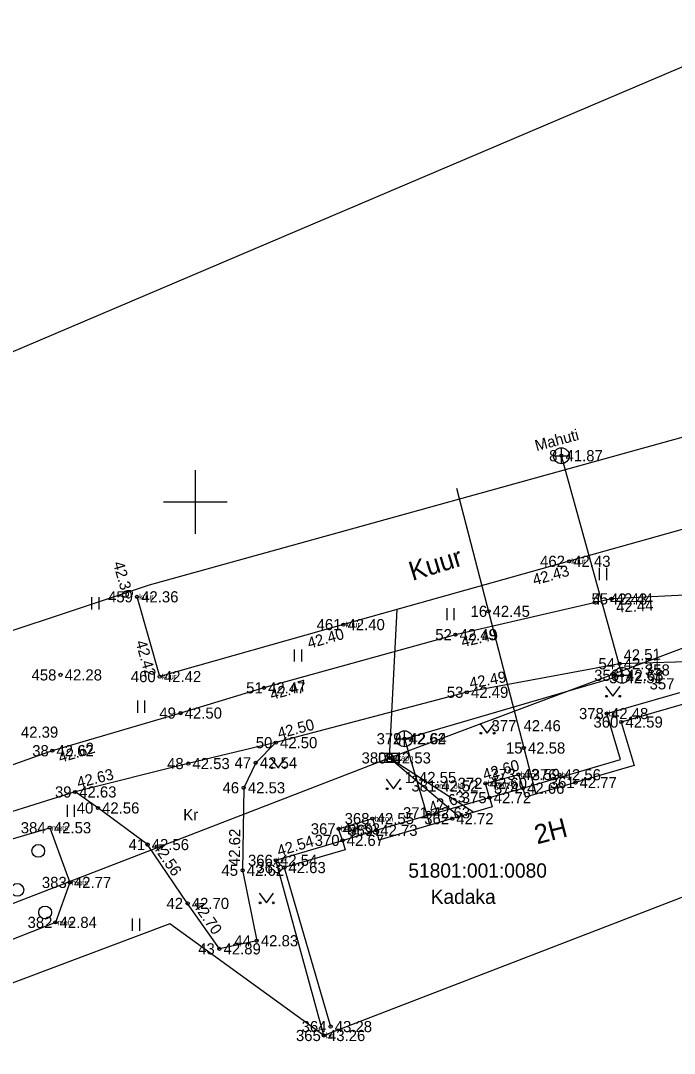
# Model space of a CAD drawing. Extents: x 505800 to 507326, y 6540058 to 6542128.
# Drawn here: x 506089 to 506130.1, y 6540215.4 to 6540280.2 of the extents above; entities that cross this region are included whole.
import ezdxf

# ---------------------------------------------------------------- set-up
doc = ezdxf.new("R2010")
doc.units = 0
for name, color, linetype in [('ELRAJATISMP', 7, 'Continuous'), ('HALJASTUS', 7, 'Continuous'), ('HOONE', 7, 'Continuous'), ('HOONEDET', 7, 'Continuous'), ('KKAEV', 7, 'Continuous'), ('KORGUS-EH2000', 7, 'Continuous'), ('KTRASS', 7, 'Continuous'), ('MAAMUDEL', 7, 'Continuous'), ('MOOTKORG-EH2000', 7, 'Continuous'), ('MOOTMPUNKT', 7, 'Continuous'), ('MOOTNR', 7, 'Continuous'), ('MOOTPIIR', 7, 'Continuous'), ('MPKAABEL', 7, 'Continuous'), ('MPOHULIIN', 7, 'Continuous'), ('PIIR', 7, 'Continuous'), ('POST', 7, 'Continuous'), ('RAJATIS', 7, 'Continuous'), ('TEE', 7, 'Continuous'), ('VORK', 7, 'Continuous')]:
    doc.layers.add(name, color=color, linetype=linetype)

msp = doc.modelspace()

# ---------------------------------------------------------------- linework, layer by layer
at = {"layer": 'ELRAJATISMP'}
for p, q in [((506112.053, 6540234.226), (506112.053, 6540233.629)), ((506112.325, 6540234.226), (506112.325, 6540233.629))]:
    msp.add_line(p, q, dxfattribs=at)
msp.add_lwpolyline([(506111.592, 6540234.226), (506112.786, 6540234.226), (506112.786, 6540233.629), (506111.592, 6540233.629)], close=True, dxfattribs=at)
at = {"layer": 'HALJASTUS'}
for p, q in [((506125.351, 6540245.86), (506125.351, 6540245.098)), ((506125.806, 6540245.86), (506125.806, 6540245.098)), ((506093.482, 6540244.017), (506093.482, 6540243.256)), ((506093.937, 6540244.017), (506093.937, 6540243.256)), ((506115.782, 6540243.336), (506115.782, 6540242.575)), ((506116.237, 6540243.336), (506116.237, 6540242.575)), ((506106.213, 6540240.732), (506106.213, 6540239.971)), ((506106.668, 6540240.732), (506106.668, 6540239.971)), ((506125.757, 6540238.405), (506126.22, 6540237.798)), ((506126.22, 6540237.798), (506126.666, 6540238.405)), ((506096.364, 6540237.527), (506096.364, 6540236.766)), ((506096.819, 6540237.527), (506096.819, 6540236.766)), ((506117.869, 6540236.081), (506118.333, 6540235.475)), ((506118.333, 6540235.475), (506118.778, 6540236.081)), ((506104.737, 6540233.918), (506105.201, 6540233.311)), ((506105.201, 6540233.311), (506105.646, 6540233.918)), ((506111.984, 6540232.596), (506112.447, 6540231.989)), ((506112.447, 6540231.989), (506112.893, 6540232.596)), ((506091.951, 6540230.988), (506091.951, 6540230.227)), ((506092.406, 6540230.988), (506092.406, 6540230.227)), ((506104.008, 6540225.43), (506104.471, 6540224.824)), ((506104.471, 6540224.824), (506104.917, 6540225.43)), ((506096.045, 6540223.837), (506096.045, 6540223.076)), ((506096.5, 6540223.837), (506096.5, 6540223.076))]:
    msp.add_line(p, q, dxfattribs=at)
msp.add_lwpolyline([(506091.221, 6540223.598), (506086.055, 6540221.567), (506084.601, 6540227.684), (506090.863, 6540229.542), (506092.12, 6540226.107), (506091.221, 6540223.598)], dxfattribs=at)
for centre, radius in [((506125.819, 6540237.798), 0.055), ((506126.648, 6540237.798), 0.055), ((506117.932, 6540235.475), 0.055), ((506118.76, 6540235.475), 0.055), ((506104.8, 6540233.311), 0.055), ((506105.628, 6540233.311), 0.055), ((506112.046, 6540231.989), 0.055), ((506112.875, 6540231.989), 0.055), ((506090.14, 6540228.09), 0.4), ((506088.836, 6540225.641), 0.4), ((506090.575, 6540224.221), 0.4), ((506104.07, 6540224.824), 0.055), ((506104.899, 6540224.824), 0.055)]:
    msp.add_circle(centre, radius, dxfattribs=at)
at = {"layer": 'HOONE'}
for p, q in [((506130.639, 6540237.309), (506126.746, 6540236.177)), ((506123.864, 6540232.378), (506120.736, 6540231.461)), ((506118.476, 6540231.431), (506120.57, 6540232.025)), ((506120.57, 6540232.025), (506120.736, 6540231.461)), ((506118.476, 6540231.431), (506118.648, 6540230.848)), ((506118.648, 6540230.848), (506111.53, 6540228.77)), ((506109.245, 6540228.75), (506111.352, 6540229.381)), ((506111.352, 6540229.381), (506111.53, 6540228.77)), ((506109.245, 6540228.75), (506109.418, 6540228.155))]:
    msp.add_line(p, q, dxfattribs=at)
for points in [[(506132.518, 6540254.195), (506133.851, 6540249.184), (506123.465, 6540246.272), (506109.297, 6540242.297), (506097.771, 6540239.032), (506096.343, 6540244.043)], [(506126.746, 6540236.177), (506127.543, 6540233.458), (506123.864, 6540232.378)], [(506109.418, 6540228.155), (506105.588, 6540227.041), (506108.496, 6540217.056)]]:
    msp.add_lwpolyline(points, dxfattribs=at)
at = {"layer": 'HOONEDET'}
for p, q in [((506125.837, 6540236.712), (506130.426, 6540238.044)), ((506126.686, 6540233.82), (506125.837, 6540236.712)), ((506120.57, 6540232.025), (506126.686, 6540233.82)), ((506111.352, 6540229.381), (506118.476, 6540231.431)), ((506105.058, 6540227.498), (506109.245, 6540228.75)), ((506108.07, 6540216.496), (506105.058, 6540227.498))]:
    msp.add_line(p, q, dxfattribs=at)
at = {"layer": 'KKAEV'}
for p, q in [((506122.982, 6540252.403), (506122.982, 6540253.403)), ((506122.482, 6540252.903), (506123.482, 6540252.903)), ((506126.792, 6540238.616), (506126.792, 6540239.616)), ((506126.292, 6540239.116), (506127.292, 6540239.116)), ((506113.134, 6540234.63), (506113.134, 6540235.63)), ((506112.634, 6540235.13), (506113.634, 6540235.13))]:
    msp.add_line(p, q, dxfattribs=at)
for centre in [(506122.982, 6540252.903), (506126.792, 6540239.116), (506113.134, 6540235.13)]:
    msp.add_circle(centre, 0.5, dxfattribs=at)
at = {"layer": 'KORGUS-EH2000'}
for centre in [(506122.982, 6540252.903), (506123.465, 6540246.272), (506096.343, 6540244.043), (506126.133, 6540243.916), (506118.402, 6540243.131), (506109.297, 6540242.297), (506116.327, 6540241.664), (506126.638, 6540239.842), (506091.541, 6540239.138), (506097.771, 6540239.032), (506126.792, 6540239.116), (506104.313, 6540238.326), (506117.049, 6540238.049), (506099.073, 6540236.742), (506125.837, 6540236.712), (506126.746, 6540236.177), (506105.059, 6540234.886), (506113.134, 6540235.13), (506091.024, 6540234.378), (506120.624, 6540234.55), (506099.56, 6540233.572), (506103.793, 6540233.616), (506112.189, 6540233.927), (506120.291, 6540232.886), (506122.866, 6540232.868), (506113.78, 6540232.698), (506118.219, 6540232.328), (506123.864, 6540232.378), (506092.451, 6540231.789), (506103.04, 6540232.052), (506115.177, 6540232.167), (506120.57, 6540232.025), (506118.476, 6540231.431), (506093.889, 6540230.784), (506114.65, 6540230.481), (506111.125, 6540230.116), (506116.124, 6540230.107), (506090.863, 6540229.542), (506108.999, 6540229.472), (506111.352, 6540229.381), (506097.004, 6540228.485), (506109.245, 6540228.75), (506105.058, 6540227.498), (506105.588, 6540227.041), (506102.972, 6540226.871), (506092.12, 6540226.107), (506099.521, 6540224.79), (506091.221, 6540223.598), (506103.856, 6540222.445), (506101.513, 6540221.937), (506108.496, 6540217.056), (506108.07, 6540216.496)]:
    msp.add_circle(centre, 0.1, dxfattribs=at)
at = {"layer": 'KTRASS'}
for p, q in [((506116.398, 6540250.872), (506121.375, 6540231.648)), ((506113.134, 6540235.13), (506114.719, 6540229.701))]:
    msp.add_line(p, q, dxfattribs=at)
msp.add_lwpolyline([(506113.134, 6540235.13), (506126.792, 6540239.116), (506122.982, 6540252.903)], dxfattribs=at)
at = {"layer": 'MOOTMPUNKT'}
for centre in [(506122.982, 6540252.903), (506123.465, 6540246.272), (506096.343, 6540244.043), (506126.133, 6540243.916), (506118.402, 6540243.131), (506109.297, 6540242.297), (506116.327, 6540241.664), (506126.638, 6540239.842), (506091.541, 6540239.138), (506097.771, 6540239.032), (506126.792, 6540239.116), (506104.313, 6540238.326), (506117.049, 6540238.049), (506099.073, 6540236.742), (506125.837, 6540236.712), (506126.746, 6540236.177), (506105.059, 6540234.886), (506113.134, 6540235.13), (506091.024, 6540234.378), (506120.624, 6540234.55), (506099.56, 6540233.572), (506103.793, 6540233.616), (506112.189, 6540233.927), (506120.291, 6540232.886), (506122.866, 6540232.868), (506113.78, 6540232.698), (506118.219, 6540232.328), (506123.864, 6540232.378), (506092.451, 6540231.789), (506103.04, 6540232.052), (506115.177, 6540232.167), (506120.57, 6540232.025), (506118.476, 6540231.431), (506093.889, 6540230.784), (506114.65, 6540230.481), (506111.125, 6540230.116), (506116.124, 6540230.107), (506090.863, 6540229.542), (506108.999, 6540229.472), (506111.352, 6540229.381), (506097.004, 6540228.485), (506109.245, 6540228.75), (506105.058, 6540227.498), (506105.588, 6540227.041), (506102.972, 6540226.871), (506092.12, 6540226.107), (506099.521, 6540224.79), (506091.221, 6540223.598), (506103.856, 6540222.445), (506101.513, 6540221.937), (506108.496, 6540217.056), (506108.07, 6540216.496)]:
    msp.add_circle(centre, 0.1, dxfattribs=at)
at = {"layer": 'MOOTPIIR'}
for points in [[(506083.03, 6540240.114), (506097.119, 6540244.795), (506135.023, 6540255.311), (506160.43, 6540256.455), (506171.091, 6540256.503), (506184.044, 6540258.184), (506197.806, 6540260.288), (506211.896, 6540262.383), (506227.932, 6540267.786), (506240.253, 6540270.959), (506245.955, 6540263.864)], [(506248.469, 6540250.071), (506234.931, 6540239.99), (506231.591, 6540236.406), (506193.196, 6540222.875), (506188.596, 6540225.549), (506168.901, 6540229.957), (506140.91, 6540229.168), (506108.07, 6540216.496), (506098.399, 6540223.506), (506079.917, 6540216.55)]]:
    msp.add_lwpolyline(points, dxfattribs=at)
at = {"layer": 'MPKAABEL'}
for q in [(506112.67, 6540243.243), (506116.557, 6540230.238)]:
    msp.add_line((506112.189, 6540233.927), q, dxfattribs=at)
at = {"layer": 'MPOHULIIN'}
for points in [[(506112.189, 6540233.927), (506153.828, 6540249.522), (506196.936, 6540256.778), (506240.207, 6540264.027), (506283.784, 6540271.755), (506305.802, 6540315.044)], [(506023.288, 6540193.167), (506046.819, 6540209.126), (506079.898, 6540221.464), (506112.189, 6540233.927), (506117.49, 6540230.51)]]:
    msp.add_lwpolyline(points, dxfattribs=at)
at = {"layer": 'PIIR'}
msp.add_lwpolyline([(506075.94, 6540254.08), (506092.1, 6540260.96), (506133.36, 6540278.52), (506141.06, 6540246.81), (506150.17, 6540208.02), (506090.32, 6540182.64), (506081.75, 6540225.93), (506080.52, 6540231.87)], close=True, dxfattribs=at)
at = {"layer": 'POST'}
msp.add_circle((506112.189, 6540233.927), 0.25, dxfattribs=at)
at = {"layer": 'TEE'}
for points in [[(506250.031, 6540264.042), (506237.432, 6540259.066), (506223.872, 6540254.219), (506212.634, 6540251.013), (506200.022, 6540248.8), (506187.383, 6540247.629), (506174.426, 6540246.673), (506168.123, 6540246.063), (506162.988, 6540245.422), (506156.937, 6540244.719), (506147.401, 6540244.066), (506139.254, 6540244.367), (506135.743, 6540244.402), (506126.133, 6540243.916), (506116.327, 6540241.664), (506104.313, 6540238.326), (506099.073, 6540236.742), (506091.024, 6540234.378), (506084.768, 6540232.16)], [(506136.149, 6540239.864), (506135.937, 6540240.063), (506132.254, 6540239.999), (506126.638, 6540239.842), (506117.049, 6540238.049), (506105.059, 6540234.886), (506099.56, 6540233.572), (506092.451, 6540231.789), (506085.515, 6540229.625), (506076.748, 6540225.83), (506064.781, 6540220.419), (506053.702, 6540216.033), (506042.573, 6540211.964), (506030.369, 6540207.528), (506023.645, 6540204.818), (506020.115, 6540202.573), (506018.326, 6540200.153), (506016.859, 6540196.696), (506016.712, 6540193.498), (506017.316, 6540188.473)], [(506105.059, 6540234.886), (506103.793, 6540233.616), (506103.04, 6540232.052), (506102.972, 6540226.871), (506103.856, 6540222.445), (506101.513, 6540221.937), (506099.521, 6540224.79), (506097.004, 6540228.485), (506093.889, 6540230.784), (506092.451, 6540231.789)], [(506118.476, 6540231.431), (506118.219, 6540232.328), (506120.291, 6540232.886), (506120.57, 6540232.025)], [(506109.245, 6540228.75), (506108.999, 6540229.472), (506111.125, 6540230.116), (506111.352, 6540229.381)]]:
    msp.add_lwpolyline(points, dxfattribs=at)
at = {"layer": 'VORK'}
for p, q in [((506100, 6540252), (506100, 6540248)), ((506098, 6540250), (506102, 6540250))]:
    msp.add_line(p, q, dxfattribs=at)

# ---------------------------------------------------------------- texts
at = {"layer": 'HOONE'}
for s, rotation, p in [('Kuur', 17.13589, (506113.631, 6540245.037)), ('2H', 14.58957, (506121.465, 6540228.497))]:
    msp.add_text(s, height=1.2, rotation=rotation, dxfattribs=at).set_placement(p)
at = {"layer": 'KORGUS-EH2000'}
for s, p in [(' 41.87', (506122.982, 6540252.553)), (' 42.45', (506118.402, 6540242.781)), (' 42.28', (506091.541, 6540238.788)), (' 42.58', (506120.624, 6540234.2)), (' 42.55', (506113.78, 6540232.348)), (' 42.53', (506090.863, 6540229.192)), (' 42.84', (506091.221, 6540223.248)), (' 43.26', (506108.07, 6540216.146))]:
    msp.add_text(s, height=0.7, dxfattribs=at).set_placement(p)
for s, rotation, p in [(' 42.36', 285.9173, (506094.759, 6540246.406)), (' 42.43', 15.6746, (506121.035, 6540244.682)), (' 42.44', 2.89259, (506126.177, 6540243.043)), (' 42.40', 15.8138, (506106.899, 6540240.708)), (' 42.49', 12.9358, (506116.523, 6540240.811)), (' 42.42', 285.9173, (506096.171, 6540241.455)), (' 42.51', 1.5972, (506126.633, 6540240.017)), (' 42.47', 15.52901, (506104.547, 6540237.483)), (' 42.49', 10.59094, (506117.017, 6540238.221)), (' 42.50', 14.77903, (506105.014, 6540235.055)), (' 42.62', 16.36888, (506091.27, 6540233.538)), (' 42.60', 16.16953, (506117.911, 6540232.448)), (' 42.63', 14.08478, (506092.409, 6540231.958)), (' 42.63', 19.72564, (506114.572, 6540230.361)), (' 42.62', 89.24807, (506102.797, 6540226.873)), (' 42.54', 16.65504, (506105.008, 6540227.665)), (' 42.56', 304.25805, (506097.149, 6540228.584)), (' 42.70', 304.92699, (506099.664, 6540224.89))]:
    msp.add_text(s, height=0.7, rotation=rotation, dxfattribs=at).set_placement(p)
at = {"layer": 'MAAMUDEL'}
for s, p in [(' kuur', (506123.465, 6540246.098)), (' kuur', (506096.343, 6540243.868)), (' kuur', (506109.297, 6540242.122)), (' kuur', (506097.771, 6540238.857)), (' be', (506125.837, 6540236.537)), (' elkapp', (506112.189, 6540233.752)), (' beton', (506120.291, 6540232.711)), (' be', (506122.866, 6540232.693)), (' mp_ohl', (506115.177, 6540231.992)), (' beton', (506118.219, 6540232.153)), (' be', (506114.65, 6540230.306)), (' mets', (506090.863, 6540229.367)), (' beton', (506111.125, 6540229.941)), (' beton', (506108.999, 6540229.297)), (' be', (506105.058, 6540227.323)), (' mets', (506092.12, 6540225.932)), (' mets', (506091.221, 6540223.423)), (' be', (506108.07, 6540216.321))]:
    msp.add_text(s, height=0.35, dxfattribs=at).set_placement(p)
at = {"layer": 'MOOTKORG-EH2000'}
for s, p in [(' 41.87', (506122.982, 6540252.553)), (' 42.43', (506123.465, 6540245.923)), (' 42.36', (506096.343, 6540243.693)), (' 42.43', (506125.771, 6540243.551)), (' 42.44', (506126.133, 6540243.566)), (' 42.45', (506118.402, 6540242.781)), (' 42.40', (506109.297, 6540241.947)), (' 42.49', (506116.327, 6540241.314)), (' 42.51', (506126.638, 6540239.492)), (' 42.28', (506091.541, 6540238.788)), (' 42.68', (506126.792, 6540238.766)), (' 42.42', (506097.771, 6540238.683)), (' 42.51', (506126.752, 6540238.615)), (' 42.47', (506104.313, 6540237.976)), (' 42.49', (506117.049, 6540237.699)), (' 42.50', (506099.073, 6540236.392)), (' 42.48', (506125.837, 6540236.362)), (' 42.46', (506120.346, 6540235.598)), (' 42.59', (506126.746, 6540235.827)), (' 42.39', (506088.794, 6540235.195)), (' 42.50', (506105.059, 6540234.536)), (' 42.62', (506113.134, 6540234.78)), (' 42.64', (506113.178, 6540234.786)), (' 42.58', (506120.624, 6540234.2)), (' 42.62', (506091.024, 6540234.028)), (' 42.53', (506112.189, 6540233.577)), (' 42.53', (506099.56, 6540233.222)), (' 42.54', (506103.793, 6540233.266)), (' 42.55', (506113.78, 6540232.348)), (' 42.59', (506120.291, 6540232.536)), (' 42.56', (506122.866, 6540232.518)), (' 42.53', (506103.04, 6540231.702)), (' 42.52', (506115.177, 6540231.817)), (' 42.60', (506118.219, 6540231.978)), (' 42.66', (506120.57, 6540231.675)), (' 42.77', (506123.864, 6540232.028)), (' 42.63', (506092.451, 6540231.439)), (' 42.72', (506118.476, 6540231.081)), (' 42.56', (506093.889, 6540230.434)), (' 42.55', (506111.125, 6540229.766)), (' 42.63', (506114.65, 6540230.131)), (' 42.72', (506116.124, 6540229.757)), (' 42.53', (506090.863, 6540229.192)), (' 42.53', (506108.999, 6540229.122)), (' 42.73', (506111.352, 6540229.031)), (' 42.67', (506109.245, 6540228.4)), (' 42.56', (506097.004, 6540228.135)), (' 42.54', (506105.058, 6540227.148)), (' 42.62', (506102.972, 6540226.521)), (' 42.63', (506105.588, 6540226.691)), (' 42.77', (506092.12, 6540225.757)), (' 42.70', (506099.521, 6540224.44)), (' 42.84', (506091.221, 6540223.248)), (' 42.83', (506103.856, 6540222.095)), (' 42.89', (506101.513, 6540221.587)), (' 43.28', (506108.496, 6540216.706)), (' 43.26', (506108.07, 6540216.146))]:
    msp.add_text(s, height=0.7, dxfattribs=at).set_placement(p)
at = {"layer": 'MOOTNR'}
for s, p in [('8 ', (506122.212, 6540252.553)), ('462 ', (506121.645, 6540245.923)), ('459 ', (506094.523, 6540243.693)), ('55 ', (506124.873, 6540243.566)), ('4 ', (506124.932, 6540243.551)), ('16 ', (506117.282, 6540242.781)), ('461 ', (506107.617, 6540241.947)), ('52 ', (506115.067, 6540241.314)), ('54 ', (506125.308, 6540239.492)), ('458 ', (506089.721, 6540238.788)), ('356 ', (506125.042, 6540238.766)), ('358 ', (506128.228, 6540239.098)), ('460 ', (506095.952, 6540238.683)), ('3 ', (506125.982, 6540238.615)), ('357 ', (506128.521, 6540238.227)), ('51 ', (506103.193, 6540237.976)), ('53 ', (506115.789, 6540237.699)), ('49 ', (506097.743, 6540236.392)), ('378 ', (506124.087, 6540236.362)), ('377 ', (506118.596, 6540235.598)), ('360 ', (506124.996, 6540235.827)), ('50 ', (506103.799, 6540234.536)), ('379 ', (506111.384, 6540234.78)), ('2 ', (506112.408, 6540234.786)), ('15 ', (506119.504, 6540234.2)), ('38 ', (506089.764, 6540234.028)), ('380 ', (506110.439, 6540233.577)), ('48 ', (506098.23, 6540233.222)), ('47 ', (506102.463, 6540233.266)), ('1 ', (506113.15, 6540232.348)), ('373 ', (506118.541, 6540232.536)), ('376 ', (506121.116, 6540232.518)), ('46 ', (506101.71, 6540231.702)), ('381 ', (506113.567, 6540231.817)), ('372 ', (506116.469, 6540231.978)), ('374 ', (506118.75, 6540231.675)), ('361 ', (506122.254, 6540232.028)), ('39 ', (506091.191, 6540231.439)), ('375 ', (506116.727, 6540231.081)), ('40 ', (506092.559, 6540230.434)), ('368 ', (506109.375, 6540229.766)), ('371 ', (506113.04, 6540230.131)), ('362 ', (506114.374, 6540229.757)), ('384 ', (506089.043, 6540229.192)), ('367 ', (506107.25, 6540229.122)), ('369 ', (506109.602, 6540229.031)), ('370 ', (506107.495, 6540228.4)), ('41 ', (506095.814, 6540228.135)), ('366 ', (506103.308, 6540227.148)), ('45 ', (506101.642, 6540226.521)), ('363 ', (506103.838, 6540226.691)), ('383 ', (506090.37, 6540225.757)), ('42 ', (506098.191, 6540224.44)), ('382 ', (506089.471, 6540223.248)), ('44 ', (506102.456, 6540222.095)), ('43 ', (506100.183, 6540221.587)), ('364 ', (506106.676, 6540216.706)), ('365 ', (506106.32, 6540216.146))]:
    msp.add_text(s, height=0.7, dxfattribs=at).set_placement(p)
at = {"layer": 'PIIR'}
for s, p in [('51801:001:0080', (506113.375, 6540226.406)), ('Kadaka', (506114.777, 6540224.763))]:
    msp.add_text(s, height=0.9, dxfattribs=at).set_placement(p)
at = {"layer": 'RAJATIS'}
msp.add_text('Mahuti', height=0.7, rotation=15.03912, dxfattribs=at).set_placement((506121.425, 6540253.181))
at = {"layer": 'TEE'}
for p in [(506118.786, 6540231.868), (506109.612, 6540229.14)]:
    msp.add_text('Betoon', height=0.35, rotation=16.14147, dxfattribs=at).set_placement(p)
msp.add_text('Kr', height=0.7, dxfattribs=at).set_placement((506099.246, 6540230.011))

doc.saveas('drawing.dxf')
